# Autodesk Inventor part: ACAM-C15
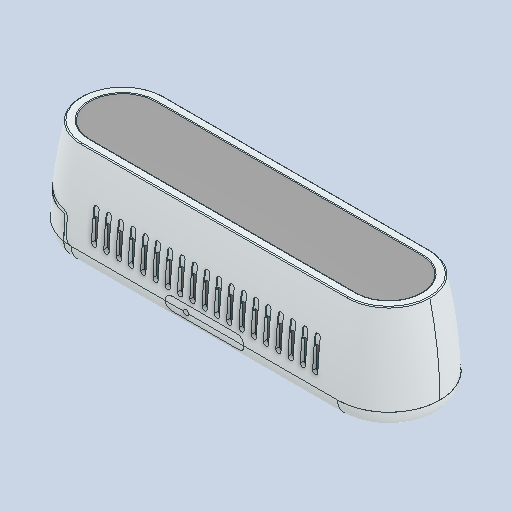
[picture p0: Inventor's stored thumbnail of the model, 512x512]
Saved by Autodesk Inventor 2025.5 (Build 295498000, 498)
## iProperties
Created: 2018-08
Part Number: ACAM-C15
Material: Genérico
Document SubType Name: Modeling
Designer: Luis MuÃ±oz
Density: 1 g/cm^3
Appearance: Valor por defecto
Project: TESIS 2 - Plataforma mecatrÃ³nica preventiva desacoplada
Description: Cámara Intel RealSense D435i
Vendor: Intel RealSense
Sending System: SolidWorks 2016
Last Author: Ancel
Last Saved: 2018-09-21
Material_BOM: Conjunto comercial
Proceso_BOM: Comercial
Author: Luis M
Title: CÃ¡mara de profundidad Intel RealSense D435i
Revision Number: 00
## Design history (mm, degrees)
thread "Split2[2]"
thread "Thread1"
thread "Cut-Extrude10[1]"
thread "Cut-Extrude10[2]"
thread "Cut-Extrude12"
node "Plane1"
node "Plane2"
node "Plane3"
node "Plane4"
node "Plane5"
node "Plane6"
node "Plane7"
node "Plane8"
node "Sólido1"
node "Sólido2"
node "Sólido3"
node "Sólido4"
node "Sólido5"
